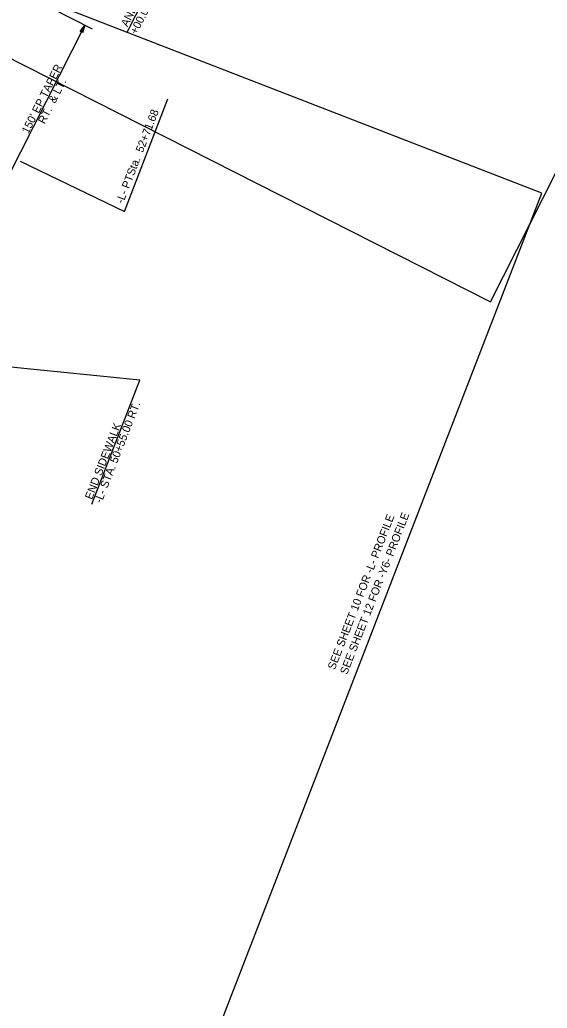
# Model space of a CAD drawing. Extents: x 1974386 to 1979988, y 776712 to 784860.
# Drawn here: x 1977931 to 1978392, y 781294 to 782159 of the extents above; entities that cross this region are included whole.
import ezdxf

# ---------------------------------------------------------------- set-up
doc = ezdxf.new("R2010")
doc.units = 0
for name, color, linetype in [('Prop Dimension', 7, 'Continuous'), ('Prop Dimension Text', 7, 'Continuous'), ('Prop DSN Text', 7, 'Continuous'), ('Prop Horizontal Alignment Station Label', 7, 'Continuous'), ('Prop Terminator CELL', 7, 'Continuous'), ('Sheet Layout Plan Border', 7, 'Continuous')]:
    doc.layers.add(name, color=color, linetype=linetype)

msp = doc.modelspace()

# ---------------------------------------------------------------- linework, layer by layer
at = {"layer": 'Prop Dimension'}
for p, q in [((1977994.25, 782150.84), (1977937.21, 782179.76)), ((1977987.61, 782154.21), (1977919.96, 782020.76)), ((1978035.67, 781843.7), (1977779.23, 781869.34)), ((1977993.76, 781735.2), (1978035.67, 781843.7))]:
    msp.add_line(p, q, dxfattribs=at)
at = {"layer": 'Prop DSN Text'}
msp.add_line((1978024.77, 782148.13), (1978071.95, 782241.16), dxfattribs=at)
at = {"layer": 'Prop Horizontal Alignment Station Label'}
for p, q in [((1978022.22, 781991.27), (1978060.24, 782089.68)), ((1977931.05, 782035.29), (1978022.22, 781991.27))]:
    msp.add_line(p, q, dxfattribs=at)
at = {"layer": 'Prop Terminator CELL'}
msp.add_lwpolyline([(1977983.52, 782148.71), (1977987.61, 782154.21), (1977985.61, 782147.61), (1977984.93, 782148.92)], close=True, dxfattribs=at)
at = {"layer": 'Sheet Layout Plan Border'}
for points in [[(1978342.72, 781912.24), (1978974.34, 783158.3), (1978974.34, 783158.3), (1978037.78, 783633.03), (1978037.78, 783633.03), (1977406.16, 782386.97), (1977406.16, 782386.97)], [(1977881.86, 780701.89), (1978387.67, 782007.32), (1977408.59, 782386.68), (1976902.78, 781081.25)]]:
    msp.add_lwpolyline(points, close=True, dxfattribs=at)

# ---------------------------------------------------------------- texts
at = {"layer": 'Prop Dimension Text'}
for s, rotation, p in [('AND GUARDRAIL', 63.11985, (1978024.89, 782152.18)), ('+00.00 RT.', 63.11985, (1978032.96, 782145.57)), ("150' EP TAPER", 63.1044, (1977938.1, 782058.65)), ('RT.  & LT.', 63.1044, (1977952.39, 782067.23)), ('-L- STA. 50+55.00 RT.', 68.71315, (1978002.15, 781735.51)), ('END SIDEWALK', 68.71315, (1977993.88, 781738.73))]:
    msp.add_text(s, height=7, rotation=rotation, dxfattribs=at).set_placement(p)
at = {"layer": 'Prop Horizontal Alignment Station Label'}
for s, rotation, p in [('-L- PTSta.  52+71.68', 68.87745, (1978021.08, 781997.61)), ('SEE SHEET 10 FOR -L- PROFILE', 68.75702, (1978206.41, 781589.86)), ('SEE SHEET 12 FOR -Y6- PROFILE', 68.75702, (1978217.19, 781585.68))]:
    msp.add_text(s, height=7, rotation=rotation, dxfattribs=at).set_placement(p)

doc.saveas('drawing.dxf')
